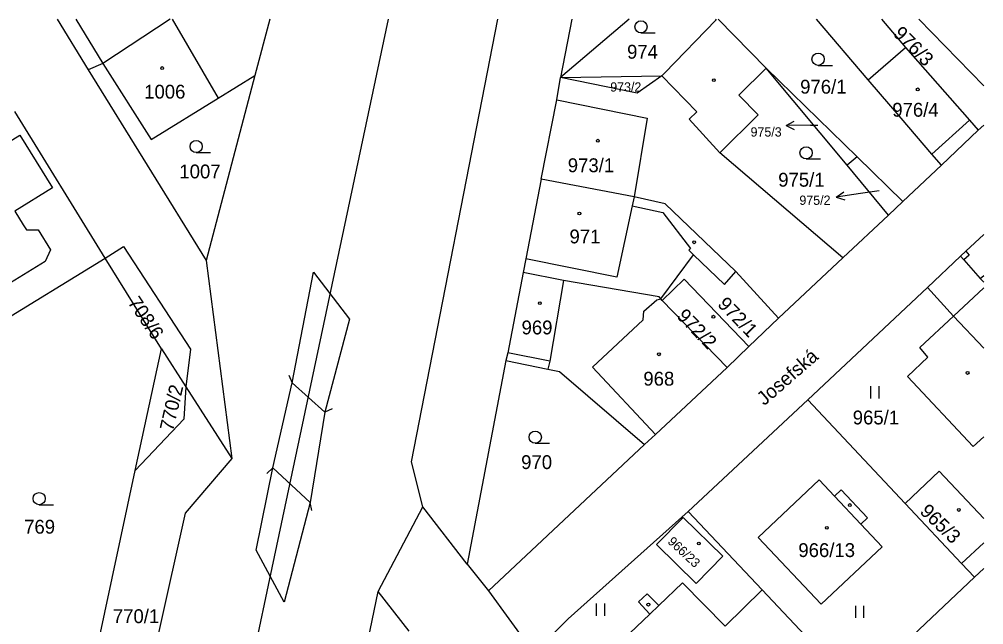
# Model space of a CAD drawing. Extents: x -776606 to -776076, y -974328 to -973875.
# Drawn here: x -776193.8 to -776075.5, y -973948.9 to -973874.5 of the extents above; entities that cross this region are included whole.
import ezdxf

# ---------------------------------------------------------------- set-up
doc = ezdxf.new("R2010")
doc.units = 0
for name, color, linetype in [('Hranice parcel', 7, 'Continuous'), ('Parcelní čísla', 7, 'Continuous'), ('Pop  PČ popisy', 7, 'Continuous'), ('Poz předměty', 7, 'Continuous'), ('Vnitřní kresba', 7, 'Continuous'), ('Značky budov', 7, 'Continuous'), ('Značky kultur', 7, 'Continuous')]:
    doc.layers.add(name, color=color, linetype=linetype)

msp = doc.modelspace()

# ---------------------------------------------------------------- linework, layer by layer
at = {"layer": 'Hranice parcel'}
for p, q in [((-776189.15, -973874.54), (-776185.35, -973880.74)), ((-776163.08, -973874.54), (-776164.9, -973881.43)), ((-776119, -973874.54), (-776127.43, -973881.7)), ((-776126.05, -973874.54), (-776127.43, -973881.7)), ((-776108.1, -973874.54), (-776102.18, -973880.53)), ((-776075.52, -973882.72), (-776083.47, -973874.54)), ((-776183.56, -973879.96), (-776185.35, -973880.74)), ((-776185.35, -973880.74), (-776170.9, -973904.16)), ((-776092.25, -973892.45), (-776102.18, -973880.53)), ((-776102.18, -973880.53), (-776091.04, -973891.43)), ((-776164.9, -973881.43), (-776170.9, -973904.16)), ((-776127.43, -973881.7), (-776115, -973881.5)), ((-776183.26, -973903.85), (-776194.35, -973885.85)), ((-776075.52, -973887.54), (-776076.18, -973888.17)), ((-776076.18, -973888.17), (-776080.71, -973892.46)), ((-776091.04, -973891.43), (-776092.25, -973892.45)), ((-776091.04, -973891.43), (-776085.43, -973896.92)), ((-776087.19, -973898.58), (-776092.25, -973892.45)), ((-776080.71, -973892.46), (-776085.43, -973896.92)), ((-776085.43, -973896.92), (-776087.19, -973898.58)), ((-776087.19, -973898.58), (-776092.78, -973903.83)), ((-776075.52, -973900.95), (-776077.71, -973903.02)), ((-776183.26, -973903.85), (-776181.01, -973902.43)), ((-776176.37, -973914.99), (-776183.26, -973903.85)), ((-776170.9, -973904.16), (-776167.74, -973928.46)), ((-776092.78, -973903.83), (-776100.68, -973911.21)), ((-776127.06, -973906.61), (-776131.99, -973905.62)), ((-776100.68, -973911.21), (-776105.9, -973905.49)), ((-776082.42, -973907.47), (-776097.07, -973921.25)), ((-776082.42, -973907.47), (-776079.23, -973910.97)), ((-776114.94, -973909.04), (-776115.12, -973908.86)), ((-776106.98, -973917.29), (-776114.94, -973909.04)), ((-776100.68, -973911.21), (-776104.32, -973914.72)), ((-776079.23, -973910.97), (-776075.52, -973914.92)), ((-776179.58, -973929.94), (-776176.37, -973914.99)), ((-776176.37, -973914.99), (-776173.38, -973919.66)), ((-776104.32, -973914.72), (-776106.98, -973917.29)), ((-776134.12, -973916.43), (-776138.86, -973941.44)), ((-776134.12, -973916.43), (-776128.96, -973917.47)), ((-776173.38, -973919.66), (-776167.74, -973928.46)), ((-776097.07, -973921.25), (-776111.76, -973934.97)), ((-776097.07, -973921.25), (-776085.15, -973933.96)), ((-776117.13, -973926.74), (-776136.26, -973944.7)), ((-776189.59, -973976.54), (-776179.58, -973929.94)), ((-776078.22, -973941.34), (-776085.15, -973933.96)), ((-776149.78, -973944.77), (-776144.3, -973934.4)), ((-776138.86, -973941.44), (-776144.3, -973934.4)), ((-776111.76, -973934.97), (-776102.68, -973944.59)), ((-776138.86, -973941.44), (-776136.26, -973944.7)), ((-776078.22, -973941.34), (-776076.65, -973943.02)), ((-776076.65, -973943.02), (-776075.52, -973941.95)), ((-776076.65, -973943.02), (-776091.19, -973956.75)), ((-776145.99, -973949.66), (-776149.78, -973944.77)), ((-776136.26, -973944.7), (-776130.7, -973952.3)), ((-776102.68, -973944.59), (-776107.23, -973949.03)), ((-776102.68, -973944.59), (-776091.19, -973956.75))]:
    msp.add_line(p, q, dxfattribs=at)
for points in [[(-776175.3, -973874.54), (-776183.56, -973879.96)], [(-776144.3, -973934.4), (-776145.69, -973928.87), (-776135.09, -973874.54)], [(-776115, -973881.5), (-776114.61, -973881.1), (-776108.39, -973874.65), (-776108.28, -973874.54)], [(-776080.71, -973892.46), (-776081.89, -973891.08), (-776085.65, -973886.69), (-776089.68, -973881.97), (-776096.04, -973874.54)], [(-776088.05, -973874.54), (-776085.09, -973878), (-776077.26, -973886.94), (-776076.18, -973888.17)], [(-776183.56, -973879.96), (-776177.64, -973889.3), (-776169.41, -973884.22), (-776164.9, -973881.43)], [(-776092.78, -973903.83), (-776107.89, -973890.94), (-776103.16, -973886.26), (-776105.53, -973883.85), (-776102.18, -973880.53)], [(-776129.79, -973894.18), (-776127.86, -973884.42), (-776127.43, -973881.7)], [(-776115, -973881.5), (-776118.04, -973883.63), (-776127.43, -973881.7)], [(-776206.39, -973905.45), (-776210.35, -973899.05), (-776193.72, -973888.77), (-776189.72, -973895.24), (-776194.36, -973898.08), (-776193.32, -973899.78), (-776192.94, -973900.4), (-776191.5, -973900.38), (-776189.96, -973902.86), (-776190.65, -973904.27), (-776198.11, -973908.86), (-776202.61, -973911.57), (-776206.39, -973905.45)], [(-776129.79, -973894.18), (-776131.67, -973903.95), (-776131.99, -973905.62)], [(-776105.9, -973905.49), (-776114.6, -973897.2), (-776118.4, -973896.32), (-776129.79, -973894.18)], [(-776181.01, -973902.43), (-776172.82, -973915.04), (-776173.38, -973919.66)], [(-776077.71, -973903.02), (-776078.35, -973903.63), (-776082.42, -973907.47)], [(-776077.71, -973903.02), (-776077.29, -973903.49), (-776077.95, -973904.08), (-776075.93, -973906.36), (-776075.52, -973905.99)], [(-776213.8, -973922.1), (-776197.17, -973912.38), (-776183.26, -973903.85)], [(-776115.12, -973908.86), (-776111.11, -973903.44), (-776107.31, -973907.11), (-776105.9, -973905.49)], [(-776131.99, -973905.62), (-776133.9, -973915.5), (-776134.12, -973916.43)], [(-776127.06, -973906.61), (-776128.75, -973916.49), (-776128.96, -973917.47)], [(-776115.12, -973908.86), (-776115.34, -973908.63), (-776127.06, -973906.61)], [(-776114.94, -973909.04), (-776112.25, -973906.44), (-776104.32, -973914.72)], [(-776075.52, -973925.78), (-776076.8, -973927), (-776084.86, -973918.37), (-776082.35, -973916), (-776083.35, -973914.81), (-776079.23, -973910.97)], [(-776128.96, -973917.47), (-776127.55, -973917.76), (-776117.13, -973926.74)], [(-776106.98, -973917.29), (-776115.79, -973925.51), (-776117.13, -973926.74)], [(-776173.38, -973919.66), (-776173.61, -973923.61), (-776179.58, -973929.94)], [(-776167.74, -973928.46), (-776173.47, -973935.17), (-776186.46, -973993.62)], [(-776085.15, -973933.96), (-776080.96, -973930.02), (-776075.52, -973935.82)], [(-776093.82, -973933.09), (-776092.98, -973932.3), (-776089.75, -973935.72), (-776090.59, -973936.52), (-776087.97, -973939.29), (-776095.44, -973946.33), (-776103.19, -973938.15), (-776095.71, -973931.09), (-776093.82, -973933.09)], [(-776130.7, -973952.3), (-776126.49, -973948.15), (-776111.76, -973934.97)], [(-776110.8, -973943.79), (-776115.66, -973939.02), (-776112.39, -973935.69), (-776107.53, -973940.46), (-776110.8, -973943.79)], [(-776075.52, -973938.8), (-776078.22, -973941.34)], [(-776168.94, -974014.19), (-776157.37, -973981.34), (-776149.78, -973944.77)], [(-776107.23, -973949.03), (-776112.46, -973943.72), (-776115.35, -973946.49), (-776116.81, -973945.05), (-776117.87, -973946.03), (-776116.47, -973947.55), (-776123.77, -973954.53), (-776118.42, -973959.96)]]:
    msp.add_lwpolyline(points, dxfattribs=at)
at = {"layer": 'Pop  PČ popisy'}
for p, q in [((-776099.76, -973887.58), (-776098.77, -973887.06)), ((-776096.76, -973887.53), (-776099.76, -973887.58)), ((-776099.76, -973887.58), (-776098.75, -973888.07)), ((-776096.76, -973887.53), (-776095.88, -973887.53)), ((-776093.6, -973896.36), (-776092.68, -973895.72)), ((-776090.63, -973895.94), (-776093.6, -973896.36)), ((-776088.33, -973895.61), (-776090.63, -973895.94)), ((-776093.6, -973896.36), (-776092.54, -973896.71))]:
    msp.add_line(p, q, dxfattribs=at)
at = {"layer": 'Poz předměty'}
for p, q in [((-776163.09, -973943.22), (-776148.51, -973874.54)), ((-776170.99, -973981), (-776163.09, -973943.22))]:
    msp.add_line(p, q, dxfattribs=at)
at = {"layer": 'Vnitřní kresba'}
for p, q in [((-776186.85, -973874.54), (-776183.56, -973879.96)), ((-776175.04, -973874.54), (-776169.41, -973884.22)), ((-776089.68, -973881.97), (-776085.09, -973878)), ((-776115, -973881.5), (-776110.7, -973885.9)), ((-776127.86, -973884.42), (-776116.8, -973886.7)), ((-776116.8, -973886.7), (-776118.4, -973896.32)), ((-776110.7, -973885.9), (-776111.65, -973886.8)), ((-776111.65, -973886.8), (-776107.89, -973890.94)), ((-776077.26, -973886.94), (-776081.89, -973891.08)), ((-776118.64, -973897.46), (-776120.5, -973906.19)), ((-776118.4, -973896.32), (-776118.64, -973897.46)), ((-776118.64, -973897.46), (-776114.89, -973898.26)), ((-776114.89, -973898.26), (-776111.48, -973902.67)), ((-776111.48, -973902.67), (-776111.69, -973902.88)), ((-776111.69, -973902.88), (-776111.11, -973903.44)), ((-776120.5, -973906.19), (-776131.67, -973903.95)), ((-776077.95, -973904.08), (-776078.35, -973903.63)), ((-776160.34, -973919.15), (-776157.7, -973905.58)), ((-776157.7, -973905.58), (-776153.31, -973911.37)), ((-776075.93, -973906.36), (-776075.52, -973906.82)), ((-776075.52, -973907.49), (-776079.23, -973910.97)), ((-776117.2, -973910.35), (-776115.62, -973908.99)), ((-776115.62, -973908.99), (-776115.12, -973908.86)), ((-776117.3, -973911.45), (-776117.2, -973910.35)), ((-776153.31, -973911.37), (-776156.33, -973922.78)), ((-776123.5, -973917.25), (-776117.3, -973911.45)), ((-776128.75, -973916.49), (-776133.9, -973915.5)), ((-776115.79, -973925.51), (-776123.5, -973917.25)), ((-776160.73, -973918.23), (-776160.34, -973919.15)), ((-776162.72, -973929.6), (-776160.34, -973919.15)), ((-776160.34, -973919.15), (-776156.33, -973922.78)), ((-776156.33, -973922.78), (-776158.14, -973933.84)), ((-776155.42, -973922.36), (-776156.33, -973922.78)), ((-776164.74, -973939.7), (-776162.72, -973929.6)), ((-776163.43, -973930.31), (-776162.72, -973929.6)), ((-776162.72, -973929.6), (-776158.14, -973933.84)), ((-776158.14, -973933.84), (-776161.33, -973946.08)), ((-776157.93, -973934.82), (-776158.14, -973933.84)), ((-776093.82, -973933.09), (-776090.59, -973936.52)), ((-776161.33, -973946.08), (-776164.74, -973939.7)), ((-776116.47, -973947.55), (-776115.35, -973946.49))]:
    msp.add_line(p, q, dxfattribs=at)
at = {"layer": 'Značky budov'}
for centre in [(-776176.28, -973880.53), (-776108.61, -973882.01), (-776083.61, -973883.15), (-776122.85, -973889.45), (-776125.11, -973898.38), (-776111.03, -973901.91), (-776129.95, -973909.38), (-776108.67, -973911.05), (-776115.35, -973915.66), (-776077.49, -973917.95), (-776091.93, -973934.17), (-776078.56, -973934.77), (-776094.76, -973936.96), (-776110.45, -973938.88), (-776116.65, -973946.39)]:
    msp.add_circle(centre, 0.175, dxfattribs=at)
at = {"layer": 'Značky kultur'}
for p, q in [((-776117.55, -973876.22), (-776115.8, -973876.22)), ((-776095.83, -973880.2), (-776094.08, -973880.2)), ((-776172.11, -973890.91), (-776170.36, -973890.91)), ((-776097.3, -973891.69), (-776095.55, -973891.69)), ((-776089.35, -973921.09), (-776089.35, -973919.59)), ((-776088.35, -973921.09), (-776088.35, -973919.59)), ((-776130.52, -973926.59), (-776128.77, -973926.59)), ((-776191.37, -973934.13), (-776189.62, -973934.13)), ((-776123, -973947.76), (-776123, -973946.26)), ((-776122, -973947.76), (-776122, -973946.26)), ((-776091.21, -973948.03), (-776091.21, -973946.53)), ((-776090.21, -973948.03), (-776090.21, -973946.53))]:
    msp.add_line(p, q, dxfattribs=at)
for centre in [(-776117.55, -973875.47), (-776095.83, -973879.45), (-776172.11, -973890.16), (-776097.3, -973890.94), (-776130.52, -973925.84), (-776191.37, -973933.38)]:
    msp.add_circle(centre, 0.75, dxfattribs=at)

# ---------------------------------------------------------------- texts
at = {"layer": 'Parcelní čísla'}
for s, height, rotation, p in [('976/3', 1.7, 315, (-776086.73, -973876.42)), ('708/6', 1.7, 304, (-776180.56, -973909.3)), ('972/1', 1.7, 314, (-776108.26, -973909.62)), ('972/2', 1.7, 314, (-776113.27, -973911.07)), ('770/2', 1.7, 77, (-776174.95, -973925.17)), ('965/3', 1.7, 316, (-776083.45, -973935.08)), ('966/23', 1.139, 317, (-776114.36, -973938.76))]:
    msp.add_text(s, height=height, rotation=rotation, dxfattribs=at).set_placement(p)
for s, height, p in [('974', 1.7, (-776119.26, -973879.38)), ('976/1', 1.7, (-776098.03, -973883.67)), ('1006', 1.7, (-776178.49, -973884.28)), ('973/2', 1.139, (-776121.32, -973883.42)), ('976/4', 1.7, (-776086.73, -973886.5)), ('975/3', 1.139, (-776104.11, -973888.94)), ('973/1', 1.7, (-776126.53, -973893.31)), ('1007', 1.7, (-776174.17, -973894.07)), ('975/1', 1.7, (-776100.72, -973895.09)), ('975/2', 1.139, (-776098.12, -973897.32)), ('971', 1.7, (-776126.32, -973902.05)), ('969', 1.7, (-776132.2, -973913.22)), ('968', 1.7, (-776117.26, -973919.51)), ('965/1', 1.7, (-776091.58, -973924.27)), ('970', 1.7, (-776132.25, -973929.75)), ('769', 1.7, (-776193.21, -973937.68)), ('966/13', 1.7, (-776098.25, -973940.55)), ('770/1', 1.7, (-776182.33, -973948.66))]:
    msp.add_text(s, height=height, dxfattribs=at).set_placement(p)
at = {"layer": 'Pop  PČ popisy'}
msp.add_text('Josefská', height=1.7, rotation=41, dxfattribs=at).set_placement((-776102.43, -973922.03))

doc.saveas('drawing.dxf')
